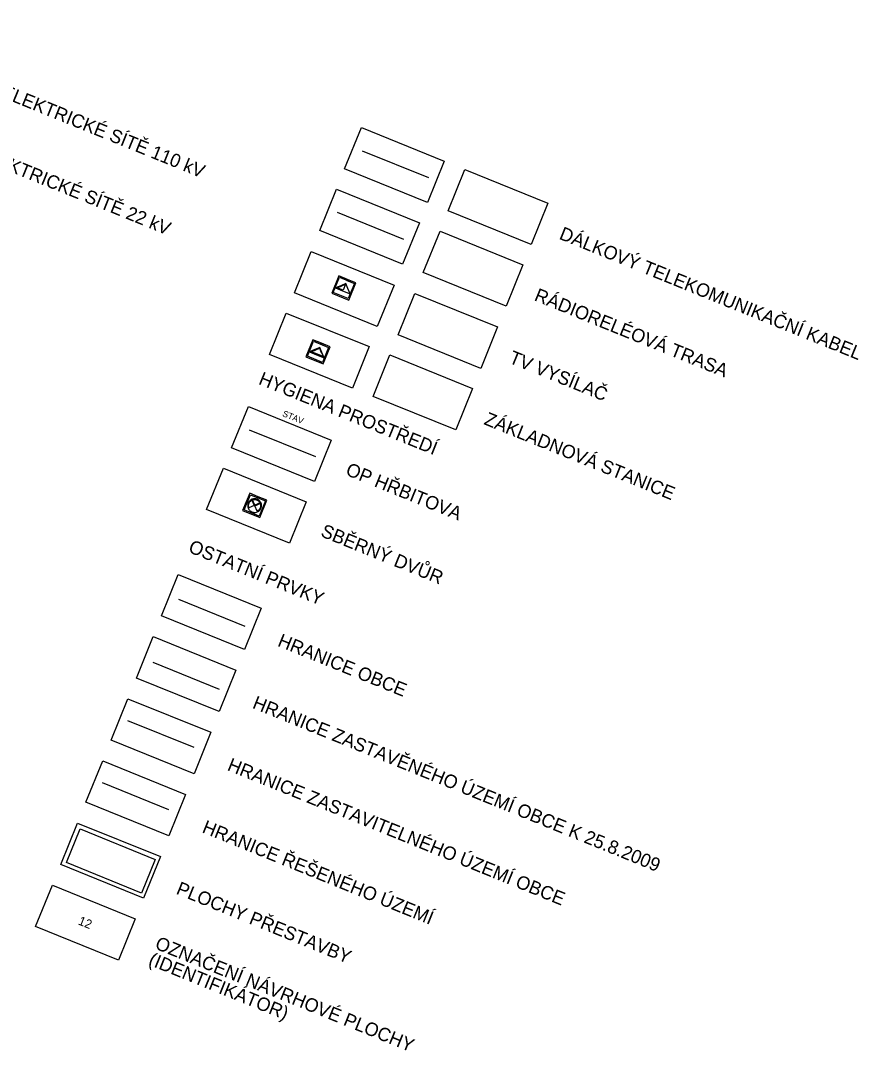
# Model space of a CAD drawing. Extents: x -522797 to -519326, y -1191143 to -1184078.
# Drawn here: x -520263 to -519326, y -1191143 to -1189991 of the extents above; entities that cross this region are included whole.
import ezdxf

# ---------------------------------------------------------------- set-up
doc = ezdxf.new("R2010")
doc.units = 0
for name, color, linetype in [('fpl_id', 7, 'Continuous'), ('hr_ku_P_s', 7, 'Continuous'), ('hr_zast_uz_P_n', 7, 'Continuous'), ('HZU_P_s', 7, 'Continuous'), ('Implicitní', 7, 'Continuous'), ('kabel_dal_s', 7, 'Continuous'), ('ložisk_nerost', 7, 'Continuous'), ('RR_trasa_s', 7, 'Continuous'), ('sberny_dvur_s', 7, 'Continuous'), ('TV_vysilac_s', 7, 'Continuous'), ('zakl_stan_s', 7, 'Continuous')]:
    doc.layers.add(name, color=color, linetype=linetype)

msp = doc.modelspace()

# ---------------------------------------------------------------- linework, layer by layer
at = {"layer": 'hr_ku_P_s'}
msp.add_line((-520086.6, -1190637.9), (-520012.5, -1190668), dxfattribs=at)
at = {"layer": 'hr_zast_uz_P_n'}
msp.add_line((-520143.6, -1190773.6), (-520069.4, -1190803.6), dxfattribs=at)
at = {"layer": 'HZU_P_s'}
msp.add_line((-520115.2, -1190708.5), (-520041.1, -1190738.6), dxfattribs=at)
at = {"layer": 'Implicitní'}
msp.add_line((-520007.6, -1190448.4), (-519933.4, -1190478.4), dxfattribs=at)
for points in [[(-519881.9, -1190110.3), (-519789.2, -1190147.8), (-519808, -1190194.2), (-519900.7, -1190156.6)], [(-519766.1, -1190157.2), (-519673.4, -1190194.8), (-519692.2, -1190241.1), (-519784.8, -1190203.6)], [(-519909.8, -1190179.1), (-519817.1, -1190216.7), (-519835.9, -1190263), (-519928.6, -1190225.5)], [(-519909.8, -1190179.1), (-519817.1, -1190216.7), (-519835.9, -1190263), (-519928.6, -1190225.5)], [(-519794, -1190226.1), (-519701.3, -1190263.7), (-519720.1, -1190310), (-519812.7, -1190272.4)], [(-519938.1, -1190248.9), (-519845.4, -1190286.5), (-519864.2, -1190332.8), (-519956.9, -1190295.2)], [(-519822.2, -1190295.8), (-519729.6, -1190333.4), (-519748.3, -1190379.7), (-519841, -1190342.2)], [(-519966, -1190317.8), (-519873.3, -1190355.3), (-519892.1, -1190401.7), (-519984.8, -1190364.1)], [(-519966, -1190317.8), (-519873.3, -1190355.3), (-519892.1, -1190401.7), (-519984.8, -1190364.1)], [(-519850.1, -1190364.7), (-519757.5, -1190402.3), (-519776.2, -1190448.6), (-519868.9, -1190411)], [(-520008.4, -1190422.5), (-519915.7, -1190460.1), (-519934.5, -1190506.4), (-520027.2, -1190468.8)], [(-520036.3, -1190491.3), (-519943.6, -1190528.9), (-519962.4, -1190575.2), (-520055.1, -1190537.7)], [(-520086.8, -1190610.3), (-519994.1, -1190647.9), (-520012.9, -1190694.2), (-520105.6, -1190656.7)], [(-520115, -1190679.8), (-520022.3, -1190717.4), (-520041.1, -1190763.7), (-520133.7, -1190726.2)], [(-520143.1, -1190749.4), (-520050.4, -1190786.9), (-520069.2, -1190833.3), (-520161.9, -1190795.7)], [(-520171.3, -1190818.9), (-520078.6, -1190856.4), (-520097.4, -1190902.8), (-520190.1, -1190865.2)], [(-520199.5, -1190888.4), (-520106.8, -1190925.9), (-520125.6, -1190972.3), (-520218.2, -1190934.7)], [(-520196.6, -1190895), (-520112.8, -1190929.2), (-520128.1, -1190966.7), (-520211.9, -1190932.5)], [(-520227.6, -1190957.9), (-520135, -1190995.4), (-520153.7, -1191041.8), (-520246.4, -1191004.2)]]:
    msp.add_lwpolyline(points, close=True, dxfattribs=at)
at = {"layer": 'kabel_dal_s'}
msp.add_line((-519881.1, -1190136.2), (-519806.9, -1190166.2), dxfattribs=at)
at = {"layer": 'ložisk_nerost'}
msp.add_line((-520171.8, -1190843.1), (-520097.6, -1190873.1), dxfattribs=at)
at = {"layer": 'RR_trasa_s'}
msp.add_line((-519909, -1190205), (-519834.8, -1190235.1), dxfattribs=at)
at = {"layer": 'sberny_dvur_s'}
for points in [[(-519997.3, -1190523.4), (-520006.9, -1190519.5), (-520014.8, -1190538.7), (-519995.5, -1190546.6), (-519987.7, -1190527.3), (-519997.3, -1190523.4)], [(-520006.2, -1190521.1), (-519989.3, -1190528), (-519996.2, -1190544.9), (-520013.1, -1190538), (-520006.2, -1190521.1)], [(-519997.8, -1190524.6), (-519989.3, -1190528), (-519996.2, -1190544.9), (-520013.1, -1190538), (-520006.2, -1190521.1), (-519997.8, -1190524.6)], [(-519998.6, -1190526.1), (-519998.8, -1190526), (-519999.7, -1190525.7), (-520000.7, -1190525.6), (-520001.7, -1190525.6), (-520002.6, -1190525.6), (-520003.6, -1190525.9), (-520004.5, -1190526.2), (-520005.4, -1190526.6), (-520006.2, -1190527.2), (-520006.9, -1190527.8), (-520007.5, -1190528.5), (-520008.1, -1190529.4), (-520008.5, -1190530.2), (-520008.5, -1190530.3)], [(-520003.8, -1190526.9), (-520002.8, -1190526.6), (-520002, -1190526.5), (-520001.1, -1190526.5), (-520000.3, -1190526.6), (-519999.5, -1190526.8), (-519998.9, -1190527)], [(-520001.3, -1190532.8), (-520003.8, -1190526.9)], [(-519998.5, -1190526.1), (-519998.9, -1190527)], [(-519998.9, -1190527), (-519998.6, -1190526.1)], [(-519994.1, -1190535.5), (-519993.9, -1190534.6), (-519993.8, -1190533.6), (-519993.8, -1190532.6), (-519993.9, -1190531.7), (-519994.2, -1190530.7), (-519994.6, -1190529.8), (-519995.1, -1190529), (-519995.6, -1190528.2), (-519996.3, -1190527.5), (-519997.1, -1190526.9), (-519997.9, -1190526.4), (-519998.5, -1190526.1)], [(-519997.3, -1190523.4), (-519997.8, -1190524.6)], [(-519997.8, -1190524.6), (-519997.3, -1190523.4)], [(-520008.8, -1190531), (-520009, -1190531.9), (-520009.1, -1190532.9), (-520009.1, -1190533.9), (-520009, -1190534.8), (-520008.7, -1190535.8), (-520008.3, -1190536.7), (-520007.9, -1190537.5), (-520007.3, -1190538.3), (-520006.6, -1190539), (-520005.8, -1190539.6), (-520005, -1190540.1), (-520004.4, -1190540.4)], [(-520008.6, -1190530.3), (-520008.8, -1190531), (-520008.8, -1190531)], [(-520007.7, -1190530.7), (-520008.6, -1190530.3)], [(-520008.5, -1190530.3), (-520007.7, -1190530.6)], [(-520007.8, -1190535.6), (-520008, -1190535), (-520008.1, -1190534.1), (-520008.2, -1190533.3), (-520008.1, -1190532.4), (-520008, -1190531.6), (-520007.9, -1190531.4)], [(-520007.9, -1190531.4), (-520007.7, -1190530.7)], [(-520001.9, -1190533.1), (-520007.8, -1190535.6)], [(-520007.7, -1190530.6), (-520007.4, -1190530.1)], [(-520007.4, -1190530.1), (-520007, -1190529.4), (-520006.5, -1190528.7), (-520005.8, -1190528.1), (-520005.2, -1190527.6), (-520004.4, -1190527.2)], [(-520004.4, -1190527.2), (-520001.9, -1190533.1)], [(-520004.3, -1190540.4), (-520004.1, -1190540.5), (-520003.2, -1190540.7), (-520002.2, -1190540.9), (-520001.2, -1190540.9), (-520000.3, -1190540.8), (-519999.3, -1190540.6), (-519998.4, -1190540.3), (-519997.5, -1190539.9), (-519996.7, -1190539.3), (-519996, -1190538.7), (-519995.4, -1190537.9), (-519994.8, -1190537.1), (-519994.4, -1190536.3), (-519994.1, -1190535.6)], [(-519995.3, -1190530.3), (-520001.3, -1190532.8)], [(-520001.1, -1190533.4), (-519995.1, -1190530.9)], [(-519998.6, -1190539.3), (-520001.1, -1190533.4)], [(-519998.9, -1190527), (-519998.7, -1190527.1), (-519997.9, -1190527.5), (-519997.2, -1190528), (-519996.6, -1190528.6), (-519996, -1190529.2), (-519995.3, -1190530.3)], [(-519995, -1190535.2), (-519995.2, -1190535.8), (-519995.5, -1190536.4), (-519995.9, -1190537.1), (-519996.5, -1190537.8), (-519997.1, -1190538.4), (-519997.7, -1190538.9), (-519998.6, -1190539.3)], [(-519995.1, -1190530.9), (-519994.8, -1190532.4), (-519994.7, -1190533.2), (-519994.8, -1190534.1), (-519994.9, -1190534.9), (-519995, -1190535.2)], [(-519994.1, -1190535.6), (-519995, -1190535.2)], [(-519995, -1190535.2), (-519994.1, -1190535.5)], [(-520004.4, -1190540.4), (-520004.3, -1190540.4)]]:
    msp.add_lwpolyline(points, dxfattribs=at)
at = {"layer": 'TV_vysilac_s'}
for points in [[(-519897.7, -1190280.1), (-519907.3, -1190276.2), (-519915.1, -1190295.4), (-519895.9, -1190303.3), (-519888.1, -1190284), (-519897.7, -1190280.1)], [(-519906.6, -1190277.8), (-519889.7, -1190284.7), (-519896.6, -1190301.6), (-519913.5, -1190294.7), (-519906.6, -1190277.8)], [(-519898.2, -1190281.3), (-519889.7, -1190284.7), (-519896.6, -1190301.6), (-519913.5, -1190294.7), (-519906.6, -1190277.8), (-519898.2, -1190281.2)], [(-519897.1, -1190290.4), (-519899.4, -1190284.9), (-519904.9, -1190287.2)], [(-519897.7, -1190280.1), (-519898.2, -1190281.3)], [(-519898.2, -1190281.2), (-519897.7, -1190280.1)], [(-519904.9, -1190287.2), (-519910.8, -1190289.7)], [(-519910.8, -1190289.7), (-519903, -1190292.9)], [(-519909.1, -1190289.6), (-519904.7, -1190287.7)], [(-519902.4, -1190292.3), (-519909.1, -1190289.6)], [(-519904.9, -1190287.2), (-519904.7, -1190287.7)], [(-519904.7, -1190287.7), (-519904.9, -1190287.2)], [(-519904.7, -1190287.7), (-519899.7, -1190285.6)], [(-519903, -1190292.9), (-519894.6, -1190296.3)], [(-519899.7, -1190285.6), (-519902.4, -1190292.3)], [(-519894.6, -1190296.3), (-519897.1, -1190290.4)]]:
    msp.add_lwpolyline(points, dxfattribs=at)
at = {"layer": 'zakl_stan_s'}
for points in [[(-519926.7, -1190351.5), (-519936.3, -1190347.6), (-519944.1, -1190366.9), (-519924.8, -1190374.7), (-519917, -1190355.5), (-519926.7, -1190351.6)], [(-519935.6, -1190349.3), (-519918.7, -1190356.2), (-519925.5, -1190373.1), (-519942.4, -1190366.2), (-519935.6, -1190349.3)], [(-519927.1, -1190352.7), (-519918.7, -1190356.2), (-519925.5, -1190373.1), (-519942.4, -1190366.2), (-519935.6, -1190349.3), (-519927.2, -1190352.7)], [(-519927.2, -1190352.7), (-519926.7, -1190351.5)], [(-519926.7, -1190351.6), (-519927.1, -1190352.7)], [(-519934, -1190358.7), (-519939.9, -1190361.2)], [(-519939.9, -1190361.2), (-519932.2, -1190364.4)], [(-519938.3, -1190361.1), (-519933.8, -1190359.2)], [(-519931.2, -1190364), (-519938.3, -1190361.1)], [(-519926.3, -1190361.9), (-519928.6, -1190356.4), (-519934, -1190358.7)], [(-519933.8, -1190359.2), (-519928.9, -1190357.1)], [(-519932.2, -1190364.4), (-519923.8, -1190367.8)], [(-519924.9, -1190366.6), (-519931.2, -1190364)], [(-519928.9, -1190357.1), (-519926.8, -1190362.1)], [(-519926.8, -1190362.1), (-519926.3, -1190361.9)], [(-519926.3, -1190361.9), (-519926.7, -1190362.1)], [(-519926.7, -1190362.1), (-519924.9, -1190366.6)], [(-519923.8, -1190367.8), (-519926.3, -1190361.9)]]:
    msp.add_lwpolyline(points, dxfattribs=at)

# ---------------------------------------------------------------- texts
at = {"layer": 'fpl_id'}
msp.add_text('12', height=10, rotation=337.938, dxfattribs=at).set_placement((-520199.6, -1191001.6))
at = {"layer": 'Implicitní'}
for s, height, rotation, p in [('VENKOVNÍ VEDENÍ ELEKTRICKÉ SÍTĚ 110 kV', 15, 337.9379, (-520461.7, -1190004.5)), ('VENKOVNÍ VEDENÍ ELEKTRICKÉ SÍTĚ 22 kV', 15, 337.9379, (-520489.6, -1190072.7)), ('DÁLKOVÝ TELEKOMUNIKAČNÍ KABEL', 15, 337.9379, (-519661.7, -1190234.6)), ('RÁDIORELÉOVÁ TRASA', 15, 337.9379, (-519689.6, -1190303.4)), ('TV VYSÍLAČ', 15, 337.9379, (-519717.9, -1190373.2)), ('HYGIENA PROSTŘEDÍ', 15, 337.9381, (-519998, -1190397)), ('STAV', 7, 337.9379, (-519970.9, -1190433)), ('ZÁKLADNOVÁ STANICE', 15, 337.9379, (-519745.8, -1190442)), ('OP HŘBITOVA', 15, 337.9381, (-519900.6, -1190498.5)), ('SBĚRNÝ DVŮR', 15, 337.9381, (-519928.5, -1190567.3)), ('OSTATNÍ PRVKY', 15, 337.9381, (-520076.5, -1190584.9)), ('HRANICE OBCE', 15, 337.9381, (-519976.7, -1190690)), ('HRANICE ZASTAVĚNÉHO ÚZEMÍ OBCE K 25.8.2009', 15, 337.9381, (-520004.9, -1190759.5)), ('HRANICE ZASTAVITELNÉHO ÚZEMÍ OBCE', 15, 337.9381, (-520033, -1190829)), ('HRANICE ŘEŠENÉHO ÚZEMÍ', 15, 337.9381, (-520061.2, -1190898.6)), ('PLOCHY PŘESTAVBY', 15, 337.8143, (-520090.2, -1190967.3)), ('OZNAČENÍ NÁVRHOVÉ PLOCHY ', 15, 337.9381, (-520113.9, -1191028.6)), ('(IDENTIFIKÁTOR)', 15, 337.9381, (-520121.2, -1191046.6))]:
    msp.add_text(s, height=height, rotation=rotation, dxfattribs=at).set_placement(p)

doc.saveas('drawing.dxf')
